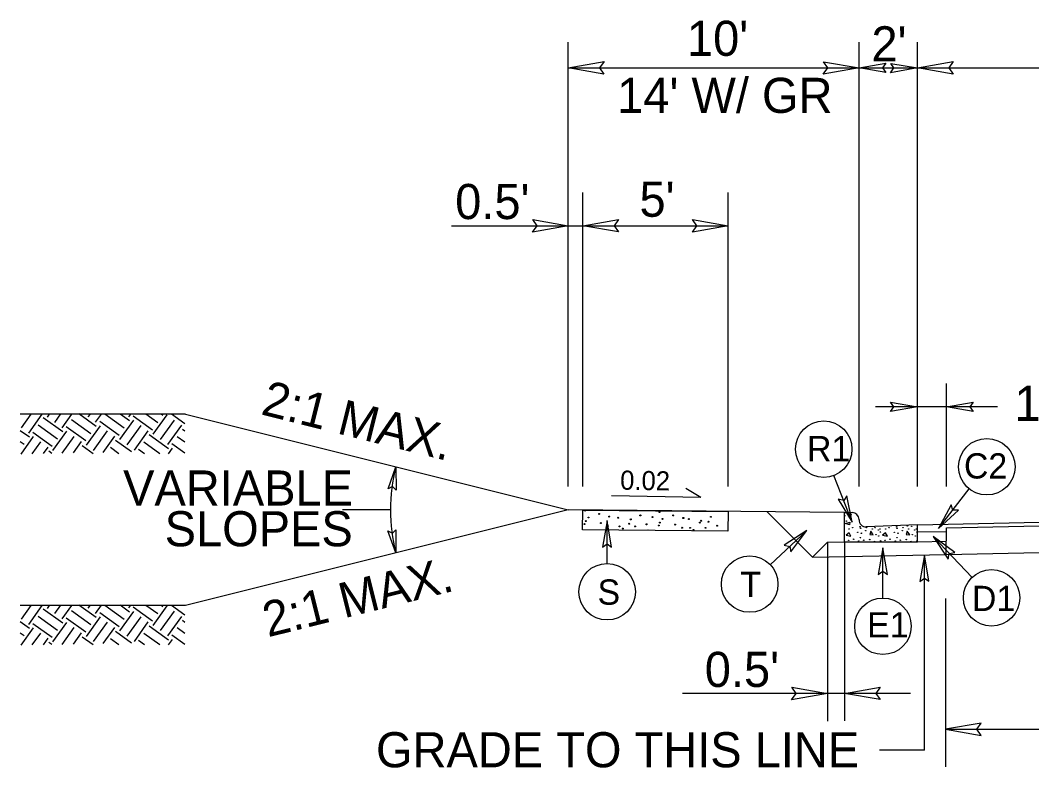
# Model space of a CAD drawing. Extents: x 3025871 to 3026431, y 707165 to 707825.
# Drawn here: x 3026298.55 to 3026333.34, y 707594.35 to 707620.09 of the extents above; entities that cross this region are included whole.
import ezdxf

# ---------------------------------------------------------------- set-up
doc = ezdxf.new("R2010")
doc.units = 0
for name, color, linetype in [('Prop Drainage Structure Junction Box with Manhole CELL', 7, 'Continuous'), ('Prop Drainage Structure Junction Box with Slab Lid TB 840 34 CELL', 7, 'Continuous'), ('Prop Drainage Structure Plot Symbol 50 Scale', 7, 'Continuous'), ('Prop Pavement Schedule Description CELL', 7, 'Continuous'), ('Sheet Plot Border Inside CELL', 7, 'Continuous'), ('Sheet Sticker Incomplete CELL', 7, 'Continuous'), ('Sheet Typical CELL', 7, 'Continuous'), ('Typical Arrow Superelevation CELL', 7, 'Continuous'), ('Typical Grade Point Symbol CELL', 7, 'Continuous'), ('Typical Text Centerline CELL', 7, 'Continuous'), ('Typical Text Grade Point CELL', 7, 'Continuous')]:
    doc.layers.add(name, color=color, linetype=linetype)

msp = doc.modelspace()

# ---------------------------------------------------------------- linework, layer by layer
at = {"layer": 'Prop Drainage Structure Junction Box with Manhole CELL'}
msp.add_line((3026325.794, 707601.603), (3026330.399, 707601.696), dxfattribs=at)
at = {"layer": 'Prop Drainage Structure Junction Box with Slab Lid TB 840 34 CELL'}
for p, q in [((3026317.398, 707604.029), (3026317.398, 707619.333)), ((3026327.398, 707604.029), (3026327.398, 707619.333)), ((3026329.404, 707604.029), (3026329.404, 707619.333)), ((3026317.398, 707618.441), (3026327.902, 707618.441)), ((3026327.902, 707618.441), (3026394.92, 707618.441)), ((3026317.898, 707604.029), (3026317.898, 707614.159)), ((3026322.898, 707604.029), (3026322.898, 707614.159)), ((3026313.383, 707613.011), (3026322.898, 707613.011)), ((3026330.403, 707604.029), (3026330.403, 707607.582)), ((3026332.159, 707606.777), (3026327.965, 707606.777)), ((3026311.283, 707603.229), (3026309.627, 707603.229)), ((3026326.311, 707602.12), (3026326.311, 707595.956)), ((3026326.896, 707602.132), (3026326.896, 707595.968)), ((3026330.369, 707600.175), (3026330.369, 707594.384)), ((3026329.166, 707596.912), (3026321.324, 707596.912)), ((3026330.369, 707595.674), (3026352.303, 707595.674)), ((3026329.65, 707594.957), (3026328.1, 707594.957))]:
    msp.add_line(p, q, dxfattribs=at)
msp.add_arc((3026317.398, 707603.229), 6.116, 165.9638, 194.0362, dxfattribs=at)
at = {"layer": 'Prop Drainage Structure Plot Symbol 50 Scale'}
for p, q in [((3026326.896, 707602.132), (3026326.896, 707603.136)), ((3026326.896, 707603.136), (3026327.157, 707603.136)), ((3026326.932, 707602.756), (3026327.087, 707602.801)), ((3026327.087, 707602.801), (3026327.07, 707602.71)), ((3026327.397, 707602.885), (3026327.397, 707602.895)), ((3026327.07, 707602.71), (3026326.932, 707602.756)), ((3026329.404, 707602.717), (3026327.648, 707602.644)), ((3026327.803, 707602.493), (3026327.768, 707602.379)), ((3026327.889, 707602.373), (3026327.803, 707602.493)), ((3026329.056, 707602.493), (3026329.022, 707602.379)), ((3026329.143, 707602.373), (3026329.056, 707602.493)), ((3026329.404, 707602.132), (3026329.404, 707602.717)), ((3026326.896, 707602.132), (3026329.404, 707602.132)), ((3026327.059, 707602.436), (3026326.955, 707602.361)), ((3026326.955, 707602.361), (3026327.121, 707602.321)), ((3026327.121, 707602.321), (3026327.059, 707602.436)), ((3026327.768, 707602.379), (3026327.889, 707602.373)), ((3026328.312, 707602.436), (3026328.209, 707602.361)), ((3026328.209, 707602.361), (3026328.375, 707602.321)), ((3026328.375, 707602.321), (3026328.312, 707602.436)), ((3026329.022, 707602.379), (3026329.143, 707602.373))]:
    msp.add_line(p, q, dxfattribs=at)
for centre in [(3026326.909, 707603.025), (3026326.961, 707602.842), (3026327.127, 707603.06), (3026327.058, 707602.568), (3026327.179, 707602.619), (3026327.356, 707602.453), (3026327.436, 707602.647), (3026327.453, 707602.597), (3026327.631, 707602.511), (3026327.66, 707602.613), (3026327.855, 707602.573), (3026327.952, 707602.616), (3026328.061, 707602.533), (3026328.117, 707602.568), (3026328.134, 707602.47), (3026328.312, 707602.568), (3026328.432, 707602.619), (3026328.61, 707602.453), (3026328.69, 707602.647), (3026328.707, 707602.597), (3026328.885, 707602.511), (3026328.913, 707602.613), (3026329.062, 707602.676), (3026329.108, 707602.573), (3026329.205, 707602.659), (3026329.314, 707602.533), (3026329.371, 707602.568), (3026329.388, 707602.47), (3026327.041, 707602.178), (3026327.213, 707602.218), (3026327.39, 707602.155), (3026327.448, 707602.27), (3026327.482, 707602.425), (3026327.562, 707602.184), (3026327.769, 707602.207), (3026327.929, 707602.138), (3026327.98, 707602.373), (3026328.077, 707602.327), (3026328.14, 707602.161), (3026328.295, 707602.178), (3026328.466, 707602.218), (3026328.644, 707602.155), (3026328.701, 707602.27), (3026328.736, 707602.425), (3026328.816, 707602.184), (3026329.022, 707602.207), (3026329.183, 707602.138), (3026329.234, 707602.373), (3026329.331, 707602.327), (3026329.394, 707602.161)]:
    msp.add_circle(centre, 0.00805, dxfattribs=at)
for centre, start, end in [((3026327.157, 707602.895), 0, 90), ((3026327.638, 707602.885), 180, 272.3845)]:
    msp.add_arc(centre, 0.24, start, end, dxfattribs=at)
at = {"layer": 'Prop Pavement Schedule Description CELL'}
for p, q in [((3026329.404, 707602.717), (3026353.412, 707603.198)), ((3026330.404, 707602.612), (3026352.413, 707603.053)), ((3026329.404, 707602.467), (3026330.403, 707602.487)), ((3026330.399, 707601.696), (3026330.404, 707602.612)), ((3026329.404, 707602.134), (3026330.401, 707602.154)), ((3026330.399, 707601.696), (3026352.413, 707602.136))]:
    msp.add_line(p, q, dxfattribs=at)
at = {"layer": 'Sheet Plot Border Inside CELL'}
msp.add_line((3026326.311, 707602.12), (3026326.896, 707602.132), dxfattribs=at)
at = {"layer": 'Sheet Sticker Incomplete CELL'}
for q in [(3026321.442, 707603.968), (3026318.89, 707603.714)]:
    msp.add_line((3026321.958, 707603.657), q, dxfattribs=at)
at = {"layer": 'Sheet Typical CELL'}
for p, q in [((3026326.896, 707603.136), (3026317.398, 707603.229)), ((3026317.885, 707602.547), (3026317.898, 707603.224)), ((3026317.898, 707603.224), (3026322.898, 707603.175)), ((3026322.898, 707603.175), (3026322.885, 707602.498)), ((3026325.794, 707601.603), (3026324.236, 707603.162)), ((3026322.885, 707602.498), (3026317.885, 707602.547)), ((3026326.311, 707602.12), (3026325.794, 707601.603))]:
    msp.add_line(p, q, dxfattribs=at)
for centre in [(3026317.981, 707603.202), (3026320.531, 707603.152), (3026317.997, 707602.842), (3026318.093, 707602.966), (3026318.457, 707603.087), (3026318.805, 707602.999), (3026319.119, 707602.958), (3026319.547, 707602.903), (3026319.876, 707603.036), (3026320.294, 707602.981), (3026320.547, 707602.792), (3026320.643, 707602.916), (3026321.007, 707603.037), (3026321.355, 707602.949), (3026321.545, 707602.91), (3026321.925, 707602.789), (3026321.973, 707602.855), (3026322.217, 707602.818), (3026322.302, 707602.989), (3026317.96, 707602.74), (3026318.52, 707602.774), (3026318.763, 707602.666), (3026319.159, 707602.658), (3026319.272, 707602.586), (3026319.497, 707602.751), (3026319.693, 707602.659), (3026320.092, 707602.731), (3026320.51, 707602.69), (3026321.07, 707602.724), (3026321.313, 707602.616), (3026321.586, 707602.61), (3026321.699, 707602.538), (3026322.12, 707602.611), (3026322.518, 707602.684)]:
    msp.add_circle(centre, 0.0164, dxfattribs=at)
msp.add_arc((3026320.146, 707602.522), 0.0164, 7.8354, 171.0404, dxfattribs=at)
at = {"layer": 'Typical Grade Point Symbol CELL'}
for p, q in [((3026327.158, 707602.803), (3026326.535, 707604.411)), ((3026330.126, 707602.593), (3026331.191, 707603.95)), ((3026318.734, 707601.383), (3026318.733, 707602.858)), ((3026324.347, 707601.339), (3026325.604, 707602.519)), ((3026331.286, 707600.904), (3026329.947, 707602.307)), ((3026328.221, 707600.192), (3026328.22, 707601.917)), ((3026329.65, 707594.957), (3026329.646, 707601.68))]:
    msp.add_line(p, q, dxfattribs=at)
for centre in [(3026326.183, 707605.317), (3026331.792, 707604.714), (3026323.637, 707600.674), (3026318.734, 707600.411), (3026331.957, 707600.2), (3026328.221, 707599.22)]:
    msp.add_circle(centre, 0.972, dxfattribs=at)
at = {"layer": 'Typical Text Centerline CELL'}
for points in [[(3026318.623, 707618.23), (3026317.398, 707618.441), (3026318.63, 707618.659), (3026318.474, 707618.441)], [(3026326.173, 707618.652), (3026327.398, 707618.441), (3026326.166, 707618.223), (3026326.323, 707618.441)], [(3026328.317, 707618.283), (3026327.398, 707618.441), (3026328.322, 707618.604), (3026328.204, 707618.441)], [(3026328.488, 707618.599), (3026329.406, 707618.441), (3026328.482, 707618.278), (3026328.6, 707618.441)], [(3026330.631, 707618.23), (3026329.406, 707618.441), (3026330.638, 707618.659), (3026330.481, 707618.441)], [(3026316.173, 707613.222), (3026317.398, 707613.011), (3026316.166, 707612.793), (3026316.323, 707613.011)], [(3026319.123, 707612.8), (3026317.898, 707613.011), (3026319.13, 707613.228), (3026318.974, 707613.011)], [(3026321.673, 707613.222), (3026322.898, 707613.011), (3026321.666, 707612.793), (3026321.823, 707613.011)], [(3026328.485, 707606.935), (3026329.404, 707606.777), (3026328.48, 707606.613), (3026328.597, 707606.777)], [(3026331.322, 707606.618), (3026330.403, 707606.777), (3026331.327, 707606.94), (3026331.21, 707606.777)], [(3026311.201, 707603.955), (3026311.465, 707604.712), (3026311.473, 707603.905), (3026311.351, 707604.028)], [(3026326.683, 707603.594), (3026327.158, 707602.803), (3026326.978, 707603.714), (3026326.87, 707603.547)], [(3026330.565, 707603.405), (3026330.126, 707602.593), (3026330.819, 707603.213), (3026330.62, 707603.221)], [(3026318.89, 707601.948), (3026318.733, 707602.857), (3026318.572, 707601.942), (3026318.733, 707602.059)], [(3026311.468, 707602.547), (3026311.465, 707601.746), (3026311.195, 707602.505), (3026311.35, 707602.429)], [(3026325.048, 707601.782), (3026325.604, 707602.519), (3026324.827, 707602.011), (3026325.022, 707601.973)], [(3026330.689, 707601.757), (3026329.947, 707602.307), (3026330.462, 707601.534), (3026330.498, 707601.73)], [(3026328.377, 707601.007), (3026328.22, 707601.917), (3026328.059, 707601.002), (3026328.221, 707601.118)], [(3026329.803, 707600.771), (3026329.646, 707601.68), (3026329.485, 707600.766), (3026329.646, 707600.882)], [(3026325.086, 707597.123), (3026326.311, 707596.912), (3026325.079, 707596.694), (3026325.236, 707596.912)], [(3026328.121, 707596.701), (3026326.896, 707596.912), (3026328.128, 707597.13), (3026327.971, 707596.912)], [(3026331.594, 707595.885), (3026330.369, 707595.674), (3026331.601, 707595.456), (3026331.444, 707595.674)]]:
    msp.add_lwpolyline(points, close=True, dxfattribs=at)
at = {"layer": 'Typical Text Grade Point CELL'}
for p, q in [((3026304.233, 707606.52), (3026298.549, 707606.52)), ((3026304.233, 707606.52), (3026298.549, 707606.52)), ((3026298.589, 707606.05), (3026298.927, 707606.52)), ((3026298.589, 707606.05), (3026298.927, 707606.52)), ((3026298.84, 707605.87), (3026299.307, 707606.52)), ((3026298.84, 707605.87), (3026299.307, 707606.52)), ((3026300.012, 707605.915), (3026299.343, 707606.395)), ((3026300.012, 707605.915), (3026299.343, 707606.395)), ((3026299.487, 707606.418), (3026299.56, 707606.52)), ((3026299.487, 707606.418), (3026299.56, 707606.52)), ((3026299.738, 707606.238), (3026299.949, 707606.532)), ((3026299.738, 707606.238), (3026299.949, 707606.532)), ((3026299.988, 707606.058), (3026300.32, 707606.52)), ((3026299.988, 707606.058), (3026300.32, 707606.52)), ((3026300.98, 707605.852), (3026300.312, 707606.332)), ((3026300.98, 707605.852), (3026300.312, 707606.332)), ((3026301.161, 707606.103), (3026300.566, 707606.53)), ((3026301.161, 707606.103), (3026300.566, 707606.53)), ((3026300.886, 707606.426), (3026300.96, 707606.529)), ((3026300.886, 707606.426), (3026300.96, 707606.529)), ((3026301.137, 707606.246), (3026301.34, 707606.528)), ((3026301.137, 707606.246), (3026301.34, 707606.528)), ((3026302.129, 707606.04), (3026301.461, 707606.52)), ((3026302.129, 707606.04), (3026301.461, 707606.52)), ((3026301.973, 707605.646), (3026302.453, 707606.314)), ((3026301.973, 707605.646), (3026302.453, 707606.314)), ((3026302.309, 707606.291), (3026301.982, 707606.526)), ((3026302.309, 707606.291), (3026301.982, 707606.526)), ((3026302.286, 707606.434), (3026302.351, 707606.525)), ((3026302.286, 707606.434), (3026302.351, 707606.525)), ((3026303.098, 707605.978), (3026302.429, 707606.458)), ((3026303.098, 707605.978), (3026302.429, 707606.458)), ((3026303.278, 707606.228), (3026302.867, 707606.524)), ((3026303.278, 707606.228), (3026302.867, 707606.524)), ((3026303.121, 707605.834), (3026303.602, 707606.502)), ((3026303.121, 707605.834), (3026303.602, 707606.502)), ((3026303.372, 707605.654), (3026303.852, 707606.322)), ((3026303.372, 707605.654), (3026303.852, 707606.322)), ((3026303.458, 707606.479), (3026303.398, 707606.522)), ((3026303.458, 707606.479), (3026303.398, 707606.522)), ((3026304.211, 707606.191), (3026303.752, 707606.521)), ((3026304.211, 707606.191), (3026303.752, 707606.521)), ((3026304.233, 707606.52), (3026317.398, 707603.229)), ((3026298.863, 707605.727), (3026298.549, 707605.953)), ((3026298.863, 707605.727), (3026298.549, 707605.953)), ((3026299.832, 707605.664), (3026299.163, 707606.144)), ((3026299.832, 707605.664), (3026299.163, 707606.144)), ((3026299.675, 707605.27), (3026300.155, 707605.938)), ((3026299.675, 707605.27), (3026300.155, 707605.938)), ((3026300.8, 707605.601), (3026300.132, 707606.082)), ((3026300.8, 707605.601), (3026300.132, 707606.082)), ((3026300.824, 707605.458), (3026301.304, 707606.126)), ((3026300.824, 707605.458), (3026301.304, 707606.126)), ((3026301.074, 707605.278), (3026301.555, 707605.946)), ((3026301.074, 707605.278), (3026301.555, 707605.946)), ((3026301.949, 707605.789), (3026301.281, 707606.27)), ((3026301.949, 707605.789), (3026301.281, 707606.27)), ((3026302.223, 707605.466), (3026302.704, 707606.134)), ((3026302.223, 707605.466), (3026302.704, 707606.134)), ((3026302.474, 707605.286), (3026302.954, 707605.954)), ((3026302.474, 707605.286), (3026302.954, 707605.954)), ((3026303.623, 707605.474), (3026304.103, 707606.142)), ((3026303.623, 707605.474), (3026304.103, 707606.142)), ((3026304.211, 707605.937), (3026304.126, 707605.998)), ((3026304.211, 707605.937), (3026304.126, 707605.998)), ((3026298.577, 707605.152), (3026299.007, 707605.75)), ((3026298.577, 707605.152), (3026299.007, 707605.75)), ((3026299.652, 707605.413), (3026298.983, 707605.894)), ((3026299.652, 707605.413), (3026298.983, 707605.894)), ((3026299.991, 707605.18), (3026300.406, 707605.758)), ((3026299.991, 707605.18), (3026300.406, 707605.758)), ((3026301.405, 707605.208), (3026301.805, 707605.766)), ((3026301.405, 707605.208), (3026301.805, 707605.766)), ((3026302.378, 707605.228), (3026301.829, 707605.622)), ((3026302.378, 707605.228), (3026301.829, 707605.622)), ((3026303.646, 707605.33), (3026302.978, 707605.81)), ((3026303.646, 707605.33), (3026302.978, 707605.81)), ((3026304.211, 707605.557), (3026303.946, 707605.748)), ((3026304.211, 707605.557), (3026303.946, 707605.748)), ((3026298.683, 707605.476), (3026298.549, 707605.572)), ((3026298.683, 707605.476), (3026298.549, 707605.572)), ((3026298.962, 707605.159), (3026299.257, 707605.57)), ((3026298.962, 707605.159), (3026299.257, 707605.57)), ((3026299.348, 707605.167), (3026299.508, 707605.39)), ((3026299.348, 707605.167), (3026299.508, 707605.39)), ((3026299.634, 707605.173), (3026299.532, 707605.246)), ((3026299.634, 707605.173), (3026299.532, 707605.246)), ((3026300.376, 707605.188), (3026300.657, 707605.578)), ((3026300.376, 707605.188), (3026300.657, 707605.578)), ((3026301.062, 707605.16), (3026300.68, 707605.434)), ((3026301.062, 707605.16), (3026300.68, 707605.434)), ((3026301.943, 707605.16), (3026301.649, 707605.372)), ((3026301.943, 707605.16), (3026301.649, 707605.372)), ((3026302.825, 707605.16), (3026302.617, 707605.309)), ((3026302.825, 707605.16), (3026302.617, 707605.309)), ((3026303.354, 707605.16), (3026302.798, 707605.56)), ((3026303.354, 707605.16), (3026302.798, 707605.56)), ((3026303.651, 707605.16), (3026303.79, 707605.354)), ((3026303.651, 707605.16), (3026303.79, 707605.354)), ((3026304.211, 707605.177), (3026303.766, 707605.497)), ((3026304.211, 707605.177), (3026303.766, 707605.497)), ((3026317.398, 707603.229), (3026304.233, 707599.938)), ((3026304.233, 707599.938), (3026298.549, 707599.938)), ((3026304.233, 707599.938), (3026298.549, 707599.938)), ((3026298.589, 707599.468), (3026298.927, 707599.938)), ((3026298.589, 707599.468), (3026298.927, 707599.938)), ((3026298.84, 707599.288), (3026299.307, 707599.938)), ((3026298.84, 707599.288), (3026299.307, 707599.938)), ((3026300.012, 707599.332), (3026299.343, 707599.812)), ((3026300.012, 707599.332), (3026299.343, 707599.812)), ((3026299.487, 707599.836), (3026299.56, 707599.938)), ((3026299.487, 707599.836), (3026299.56, 707599.938)), ((3026299.738, 707599.656), (3026299.949, 707599.949)), ((3026299.738, 707599.656), (3026299.949, 707599.949)), ((3026299.988, 707599.476), (3026300.32, 707599.938)), ((3026299.988, 707599.476), (3026300.32, 707599.938)), ((3026300.98, 707599.269), (3026300.312, 707599.75)), ((3026300.98, 707599.269), (3026300.312, 707599.75)), ((3026301.161, 707599.52), (3026300.566, 707599.948)), ((3026301.161, 707599.52), (3026300.566, 707599.948)), ((3026300.886, 707599.844), (3026300.96, 707599.947)), ((3026300.886, 707599.844), (3026300.96, 707599.947)), ((3026301.137, 707599.664), (3026301.34, 707599.945)), ((3026301.137, 707599.664), (3026301.34, 707599.945)), ((3026301.949, 707599.207), (3026301.281, 707599.687)), ((3026301.949, 707599.207), (3026301.281, 707599.687)), ((3026302.129, 707599.458), (3026301.461, 707599.938)), ((3026302.129, 707599.458), (3026301.461, 707599.938)), ((3026301.973, 707599.063), (3026302.453, 707599.732)), ((3026301.973, 707599.063), (3026302.453, 707599.732)), ((3026302.309, 707599.708), (3026301.982, 707599.944)), ((3026302.309, 707599.708), (3026301.982, 707599.944)), ((3026302.286, 707599.852), (3026302.351, 707599.943)), ((3026302.286, 707599.852), (3026302.351, 707599.943)), ((3026303.098, 707599.395), (3026302.429, 707599.875)), ((3026303.098, 707599.395), (3026302.429, 707599.875)), ((3026303.278, 707599.646), (3026302.867, 707599.941)), ((3026303.278, 707599.646), (3026302.867, 707599.941)), ((3026303.121, 707599.251), (3026303.602, 707599.92)), ((3026303.121, 707599.251), (3026303.602, 707599.92)), ((3026303.372, 707599.071), (3026303.852, 707599.74)), ((3026303.372, 707599.071), (3026303.852, 707599.74)), ((3026303.458, 707599.896), (3026303.398, 707599.94)), ((3026303.458, 707599.896), (3026303.398, 707599.94)), ((3026304.211, 707599.608), (3026303.752, 707599.939)), ((3026304.211, 707599.608), (3026303.752, 707599.939)), ((3026298.863, 707599.144), (3026298.549, 707599.37)), ((3026298.863, 707599.144), (3026298.549, 707599.37)), ((3026299.832, 707599.081), (3026299.163, 707599.562)), ((3026299.832, 707599.081), (3026299.163, 707599.562)), ((3026299.675, 707598.687), (3026300.155, 707599.356)), ((3026299.675, 707598.687), (3026300.155, 707599.356)), ((3026300.8, 707599.019), (3026300.132, 707599.499)), ((3026300.8, 707599.019), (3026300.132, 707599.499)), ((3026300.824, 707598.875), (3026301.304, 707599.544)), ((3026300.824, 707598.875), (3026301.304, 707599.544)), ((3026301.074, 707598.695), (3026301.555, 707599.363)), ((3026301.074, 707598.695), (3026301.555, 707599.363)), ((3026302.223, 707598.883), (3026302.704, 707599.552)), ((3026302.223, 707598.883), (3026302.704, 707599.552)), ((3026302.474, 707598.703), (3026302.954, 707599.371)), ((3026302.474, 707598.703), (3026302.954, 707599.371)), ((3026303.623, 707598.891), (3026304.103, 707599.559)), ((3026303.623, 707598.891), (3026304.103, 707599.559)), ((3026304.211, 707599.355), (3026304.126, 707599.416)), ((3026304.211, 707599.355), (3026304.126, 707599.416)), ((3026298.683, 707598.893), (3026298.549, 707598.99)), ((3026298.683, 707598.893), (3026298.549, 707598.99)), ((3026298.577, 707598.569), (3026299.007, 707599.167)), ((3026298.577, 707598.569), (3026299.007, 707599.167)), ((3026298.962, 707598.577), (3026299.257, 707598.987)), ((3026298.962, 707598.577), (3026299.257, 707598.987)), ((3026299.652, 707598.831), (3026298.983, 707599.311)), ((3026299.652, 707598.831), (3026298.983, 707599.311)), ((3026299.991, 707598.597), (3026300.406, 707599.175)), ((3026299.991, 707598.597), (3026300.406, 707599.175)), ((3026300.376, 707598.605), (3026300.657, 707598.995)), ((3026300.376, 707598.605), (3026300.657, 707598.995)), ((3026301.405, 707598.626), (3026301.805, 707599.183)), ((3026301.405, 707598.626), (3026301.805, 707599.183)), ((3026302.378, 707598.645), (3026301.829, 707599.04)), ((3026302.378, 707598.645), (3026301.829, 707599.04)), ((3026303.354, 707598.577), (3026302.798, 707598.977)), ((3026303.354, 707598.577), (3026302.798, 707598.977)), ((3026303.646, 707598.748), (3026302.978, 707599.228)), ((3026303.646, 707598.748), (3026302.978, 707599.228)), ((3026304.211, 707598.975), (3026303.946, 707599.165)), ((3026304.211, 707598.975), (3026303.946, 707599.165)), ((3026299.348, 707598.584), (3026299.508, 707598.807)), ((3026299.348, 707598.584), (3026299.508, 707598.807)), ((3026299.634, 707598.59), (3026299.532, 707598.664)), ((3026299.634, 707598.59), (3026299.532, 707598.664)), ((3026301.062, 707598.577), (3026300.68, 707598.852)), ((3026301.062, 707598.577), (3026300.68, 707598.852)), ((3026301.943, 707598.577), (3026301.649, 707598.789)), ((3026301.943, 707598.577), (3026301.649, 707598.789)), ((3026302.825, 707598.577), (3026302.617, 707598.727)), ((3026302.825, 707598.577), (3026302.617, 707598.727)), ((3026303.651, 707598.577), (3026303.79, 707598.771)), ((3026303.651, 707598.577), (3026303.79, 707598.771)), ((3026304.211, 707598.595), (3026303.766, 707598.915)), ((3026304.211, 707598.595), (3026303.766, 707598.915))]:
    msp.add_line(p, q, dxfattribs=at)

# ---------------------------------------------------------------- texts
at = {"layer": 'Prop Drainage Structure Junction Box with Slab Lid TB 840 34 CELL'}
for s, height, p in [("10'", 1.2089, (3026321.48, 707618.858)), ("2'", 1.2089, (3026327.825, 707618.667)), ("14' W/ GR", 1.2089, (3026319.08, 707616.894)), ("0.5'", 1.2089, (3026313.509, 707613.239)), ("5'", 1.2089, (3026319.847, 707613.319)), ("1' MIN.", 1.2089, (3026332.746, 707606.292)), ("0.5'", 1.2089, (3026322.092, 707597.133)), ('GRADE TO THIS LINE', 1.20892, (3026310.785, 707594.367))]:
    msp.add_text(s, height=height, dxfattribs=at).set_placement(p)
at = {"layer": 'Sheet Sticker Incomplete CELL'}
msp.add_text('0.02', height=0.6583, rotation=358.9408, dxfattribs=at).set_placement((3026319.178, 707603.926))
at = {"layer": 'Typical Arrow Superelevation CELL'}
for s, p in [('R1', (3026325.609, 707604.901)), ('T', (3026323.316, 707600.227)), ('D1', (3026331.281, 707599.745))]:
    msp.add_text(s, height=0.87, rotation=360, dxfattribs=at).set_placement(p)
for s, p in [('C2', (3026331.007, 707604.308)), ('S', (3026318.405, 707599.965)), ('E1', (3026327.676, 707598.837))]:
    msp.add_text(s, height=0.87, dxfattribs=at).set_placement(p)
at = {"layer": 'Typical Text Grade Point CELL'}
for rotation, p in [(345.9638, (3026306.789, 707606.524)), (14.0362, (3026307.068, 707598.839))]:
    msp.add_text('2:1 MAX.', height=1.2089, rotation=rotation, dxfattribs=at).set_placement(p)
for s, p in [('VARIABLE', (3026302.087, 707603.377)), ('SLOPES', (3026303.516, 707601.975))]:
    msp.add_text(s, height=1.2089, dxfattribs=at).set_placement(p)

doc.saveas('drawing.dxf')
